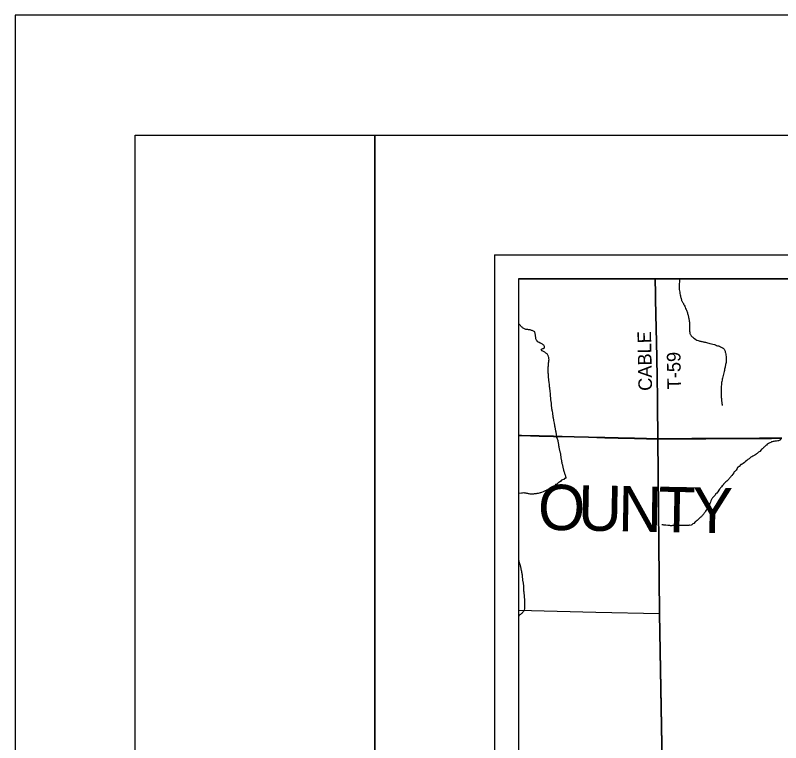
# Model space of a CAD drawing. Extents: x 0 to 34, y 0 to 22.
# Drawn here: x 0 to 3.195, y 18.962 to 22 of the extents above; entities that cross this region are included whole.
import ezdxf

# ---------------------------------------------------------------- set-up
doc = ezdxf.new("R2010")
doc.units = 0
for name, color, linetype in [('GM_X_Corporation', 7, 'Continuous'), ('GM_X_County_Text', 7, 'Continuous'), ('GM_X_Minor_River', 7, 'Continuous'), ('GM_X_Township_Road', 7, 'Continuous'), ('GM_X_Township_Road_Text', 7, 'Continuous'), ('SH_Border', 7, 'Continuous'), ('SH_Cut_Line', 7, 'Continuous'), ('SH_Data', 7, 'Continuous')]:
    doc.layers.add(name, color=color, linetype=linetype)

msp = doc.modelspace()

# ---------------------------------------------------------------- linework, layer by layer
at = {"layer": 'GM_X_Corporation'}
for points in [[(7.8853, 20.9), (2.1, 20.9), (2.1, 20.2456), (2.1124, 20.2453), (2.187, 20.2434), (2.246, 20.2419), (2.2833, 20.2411), (2.333, 20.2398), (2.3921, 20.2383), (2.4604, 20.2364), (2.5164, 20.2351), (2.535, 20.2346), (2.5847, 20.2334), (2.6344, 20.2324), (2.6825, 20.2316), (2.7333, 20.2317), (2.8234, 20.2319), (2.8825, 20.2322), (2.9354, 20.2326), (3.0007, 20.2328), (3.0286, 20.2331), (3.1064, 20.2336), (3.1561, 20.2337), (3.1996, 20.2345)], [(7.8853, 20.9), (2.6713, 20.9), (2.6715, 20.8917), (2.672, 20.8451), (2.6728, 20.814), (2.6742, 20.7519), (2.6766, 20.6339), (2.6773, 20.5717), (2.679, 20.4847), (2.6801, 20.4041), (2.6808, 20.3576), (2.6821, 20.252), (2.6825, 20.2316), (2.7333, 20.2317), (2.8234, 20.2319), (2.8825, 20.2322), (2.9354, 20.2326), (3.0007, 20.2328), (3.0286, 20.2331), (3.1064, 20.2336), (3.1561, 20.2337), (3.1996, 20.2345)], [(3.1996, 20.2345), (3.1561, 20.2337), (3.1064, 20.2336), (3.0286, 20.2331), (3.0007, 20.2328), (2.9354, 20.2326), (2.8825, 20.2322), (2.8234, 20.2319), (2.7333, 20.2317), (2.6825, 20.2316), (2.6344, 20.2324), (2.5847, 20.2334), (2.535, 20.2346), (2.5164, 20.2351), (2.4604, 20.2364), (2.3921, 20.2383), (2.333, 20.2398), (2.2833, 20.2411), (2.246, 20.2419), (2.187, 20.2434), (2.1124, 20.2453), (2.1, 20.2456), (2.1, 14.1)], [(3.1996, 20.2345), (3.1561, 20.2337), (3.1064, 20.2336), (3.0286, 20.2331), (3.0007, 20.2328), (2.9354, 20.2326), (2.8825, 20.2322), (2.8234, 20.2319), (2.7333, 20.2317), (2.6825, 20.2316), (2.6883, 19.5017), (2.7024, 18.7188), (2.7184, 17.7156), (2.7304, 16.9599), (2.7477, 15.8824), (2.7366, 15.2014)]]:
    msp.add_lwpolyline(points, dxfattribs=at)
for points in [[(2.6713, 20.9), (2.1, 20.9), (2.1, 20.2456), (2.1124, 20.2453), (2.187, 20.2434), (2.246, 20.2419), (2.2833, 20.2411), (2.333, 20.2398), (2.3921, 20.2383), (2.4604, 20.2364), (2.5164, 20.2351), (2.535, 20.2346), (2.5847, 20.2334), (2.6344, 20.2324), (2.6825, 20.2316), (2.6821, 20.252), (2.6808, 20.3576), (2.6801, 20.4041), (2.679, 20.4847), (2.6773, 20.5717), (2.6766, 20.6339), (2.6742, 20.7519), (2.6728, 20.814), (2.672, 20.8451), (2.6715, 20.8917)], [(2.1, 20.2456), (2.1, 15.2121), (2.7366, 15.2014), (2.7477, 15.8824), (2.7304, 16.9599), (2.7184, 17.7156), (2.7024, 18.7188), (2.6883, 19.5017), (2.6825, 20.2316), (2.6344, 20.2324), (2.5847, 20.2334), (2.535, 20.2346), (2.5164, 20.2351), (2.4604, 20.2364), (2.3921, 20.2383), (2.333, 20.2398), (2.2833, 20.2411), (2.246, 20.2419), (2.187, 20.2434), (2.1124, 20.2453)]]:
    msp.add_lwpolyline(points, close=True, dxfattribs=at)
at = {"layer": 'GM_X_Minor_River'}
for points in [[(2.7733, 20.9), (2.7733, 20.8993), (2.7729, 20.8944), (2.7726, 20.8898), (2.7723, 20.8852), (2.7716, 20.8803), (2.7712, 20.8757), (2.7709, 20.8715), (2.7709, 20.8677), (2.771, 20.8643), (2.771, 20.8609), (2.7714, 20.8574), (2.7714, 20.8544), (2.7719, 20.8491), (2.7731, 20.8441), (2.7739, 20.8384), (2.7751, 20.8331), (2.7759, 20.8286), (2.7771, 20.8244), (2.7779, 20.821), (2.7787, 20.8179), (2.7794, 20.8153), (2.7802, 20.8134), (2.7806, 20.8111), (2.7814, 20.8092), (2.7822, 20.8069), (2.7834, 20.8047), (2.7845, 20.8024), (2.7861, 20.8001), (2.7872, 20.7982), (2.7884, 20.796), (2.7895, 20.7941), (2.7911, 20.7918), (2.7923, 20.7888), (2.7942, 20.7854), (2.7961, 20.7812), (2.7977, 20.7759), (2.8, 20.7717), (2.8016, 20.7679), (2.8051, 20.7577), (2.8059, 20.7543), (2.8067, 20.7509), (2.8079, 20.7478), (2.8087, 20.7452), (2.8094, 20.7425), (2.8098, 20.7403), (2.8106, 20.7372), (2.8114, 20.7346), (2.8118, 20.7315), (2.8122, 20.7281), (2.813, 20.7247), (2.8131, 20.722), (2.8135, 20.7186), (2.8139, 20.7159), (2.8139, 20.7125), (2.814, 20.7083), (2.8144, 20.7045), (2.8144, 20.7003)], [(2.2041, 20.6091), (2.2071, 20.6099), (2.2086, 20.6137), (2.2086, 20.6168), (2.2074, 20.6191), (2.2055, 20.6217), (2.2032, 20.6243), (2.2005, 20.6266), (2.1978, 20.6281), (2.1951, 20.6296), (2.1932, 20.6307), (2.1906, 20.6314), (2.1871, 20.6341), (2.1841, 20.6356), (2.1814, 20.6367), (2.1775, 20.6412), (2.1752, 20.6431), (2.1733, 20.6491), (2.1725, 20.6529), (2.1721, 20.6564), (2.1717, 20.659), (2.1709, 20.6609), (2.1709, 20.6628), (2.1708, 20.6659), (2.1704, 20.6689), (2.17, 20.6708), (2.1696, 20.6727), (2.1692, 20.6754), (2.168, 20.6776), (2.1661, 20.6791), (2.1634, 20.681), (2.1577, 20.6832), (2.1543, 20.6843), (2.1516, 20.6851), (2.1486, 20.6858), (2.1459, 20.6865), (2.1436, 20.6869), (2.1417, 20.6869), (2.1398, 20.6872), (2.1368, 20.6876), (2.1337, 20.6875), (2.1315, 20.6875), (2.1276, 20.6894), (2.1253, 20.6905), (2.1223, 20.692), (2.12, 20.6935), (2.1173, 20.6954), (2.115, 20.6972), (2.1131, 20.6991), (2.1104, 20.7021), (2.1089, 20.704), (2.1066, 20.7067), (2.1046, 20.7085), (2.1031, 20.7104), (2.1004, 20.7131), (2.1, 20.7135)], [(2.8144, 20.7003), (2.8141, 20.6969), (2.8141, 20.6939), (2.8141, 20.6905), (2.8142, 20.687), (2.8142, 20.6836), (2.8142, 20.6802), (2.815, 20.6771), (2.8154, 20.6741), (2.8162, 20.6711), (2.817, 20.6688), (2.8182, 20.6665), (2.8197, 20.6639), (2.8213, 20.662), (2.8224, 20.6601), (2.8247, 20.6578), (2.8274, 20.6552), (2.8309, 20.6526), (2.8355, 20.6496), (2.8401, 20.6466), (2.845, 20.6436), (2.85, 20.6417), (2.8538, 20.6403), (2.8572, 20.6392), (2.8618, 20.6384), (2.8645, 20.6381), (2.8671, 20.6374), (2.8706, 20.6366), (2.874, 20.6363), (2.8774, 20.6352), (2.8808, 20.6345), (2.8847, 20.6334), (2.8991, 20.6293), (2.9064, 20.6275), (2.9121, 20.626), (2.9178, 20.6246), (2.9228, 20.6231), (2.9274, 20.6216), (2.9316, 20.6201), (2.9357, 20.619), (2.9396, 20.6176), (2.943, 20.6161), (2.9464, 20.6146), (2.9495, 20.6131), (2.9514, 20.612), (2.9537, 20.6105), (2.9556, 20.609), (2.9583, 20.6056), (2.9598, 20.6033), (2.961, 20.6003), (2.9626, 20.5973), (2.9634, 20.5938), (2.9645, 20.5897), (2.9654, 20.5851), (2.9662, 20.5805), (2.967, 20.5752), (2.9674, 20.571), (2.9678, 20.5669), (2.9675, 20.5631), (2.9675, 20.5589), (2.9672, 20.5543), (2.9668, 20.5501), (2.9661, 20.5459), (2.965, 20.5417), (2.9643, 20.5379), (2.9632, 20.5349), (2.9629, 20.5303), (2.9618, 20.5257), (2.9607, 20.5215), (2.9596, 20.5169), (2.9585, 20.512), (2.9574, 20.5066), (2.9559, 20.5017), (2.9548, 20.496), (2.9534, 20.4902), (2.9519, 20.4849), (2.9508, 20.4807), (2.9501, 20.4765), (2.949, 20.4708), (2.9483, 20.4666), (2.948, 20.462), (2.9462, 20.4456), (2.9463, 20.4399), (2.9463, 20.4338), (2.9464, 20.4293), (2.9464, 20.4239), (2.9465, 20.4186), (2.9466, 20.4125), (2.947, 20.408), (2.947, 20.4034), (2.9474, 20.3992), (2.9479, 20.3954), (2.9479, 20.3916), (2.9483, 20.3882), (2.9487, 20.3852), (2.9491, 20.3821), (2.9495, 20.3802), (2.9496, 20.3779), (2.9503, 20.3757), (2.9507, 20.3734), (2.9511, 20.3715)], [(2.26, 20.2397), (2.2603, 20.2345), (2.2602, 20.2429), (2.2594, 20.2478), (2.259, 20.2497), (2.2578, 20.2592), (2.2566, 20.2638), (2.2558, 20.266), (2.2554, 20.2691), (2.255, 20.2717), (2.2542, 20.2744), (2.2538, 20.2771), (2.253, 20.2805), (2.2526, 20.2839), (2.2518, 20.2892), (2.251, 20.2926), (2.2502, 20.2964), (2.2482, 20.3074), (2.2474, 20.3116), (2.2466, 20.3147), (2.2461, 20.3181), (2.2457, 20.3219), (2.2449, 20.3268), (2.2441, 20.3337), (2.2433, 20.3394), (2.2425, 20.3447), (2.2413, 20.3492), (2.2405, 20.3527), (2.2401, 20.3565), (2.2393, 20.3602), (2.2389, 20.3633), (2.2388, 20.3667), (2.2384, 20.3701), (2.238, 20.3743), (2.2376, 20.3796), (2.2367, 20.3876), (2.2359, 20.3945), (2.2355, 20.399), (2.235, 20.4032), (2.2346, 20.4066), (2.2342, 20.4093), (2.2338, 20.4127), (2.2338, 20.4169), (2.2333, 20.4222), (2.2329, 20.4272), (2.2325, 20.431), (2.2321, 20.4351), (2.2317, 20.4374), (2.2316, 20.4401), (2.2312, 20.4435), (2.2304, 20.4477), (2.23, 20.4515), (2.2296, 20.4553), (2.2291, 20.4598), (2.2283, 20.4644), (2.2279, 20.4686), (2.2275, 20.4724), (2.2271, 20.4758), (2.2267, 20.4811), (2.2262, 20.4849), (2.2262, 20.4891), (2.2258, 20.4929), (2.2254, 20.4967), (2.2249, 20.5009), (2.2245, 20.5051), (2.224, 20.5138), (2.2247, 20.5203), (2.2247, 20.5245), (2.2243, 20.5268), (2.2242, 20.5317), (2.225, 20.5367), (2.2249, 20.5401), (2.2253, 20.5428), (2.2256, 20.5454), (2.226, 20.5481), (2.226, 20.55), (2.2263, 20.5519), (2.227, 20.5595), (2.2277, 20.5618), (2.2273, 20.5671), (2.2269, 20.569), (2.2269, 20.5713), (2.2261, 20.574), (2.2245, 20.5793), (2.2234, 20.5812), (2.2218, 20.5834), (2.2195, 20.5857), (2.2172, 20.5876), (2.2149, 20.5887), (2.2115, 20.5917), (2.2096, 20.5936), (2.2073, 20.5951), (2.2054, 20.5962), (2.2023, 20.5973), (2.1996, 20.5984), (2.1973, 20.5992), (2.195, 20.6018), (2.1973, 20.6056), (2.1995, 20.6068), (2.2022, 20.608), (2.2041, 20.6091)], [(2.9511, 20.3715), (2.9515, 20.3703)], [(2.2604, 20.2397), (2.2604, 20.2373), (2.2619, 20.2312), (2.2631, 20.2282), (2.2642, 20.224), (2.2649, 20.2206), (2.2657, 20.2168), (2.2661, 20.213), (2.2668, 20.2099), (2.2672, 20.2077), (2.2676, 20.2035), (2.2683, 20.1989), (2.2687, 20.1955), (2.2695, 20.1924), (2.2702, 20.1905), (2.2706, 20.1883), (2.2714, 20.1852), (2.2721, 20.1822), (2.2729, 20.1795), (2.2733, 20.1769), (2.274, 20.1746), (2.2744, 20.1723), (2.2752, 20.17), (2.2755, 20.1677), (2.2755, 20.1654), (2.2763, 20.162), (2.2767, 20.1586), (2.277, 20.1555), (2.2774, 20.1525), (2.2789, 20.1453), (2.2793, 20.1422), (2.2801, 20.1396), (2.2804, 20.1365), (2.2812, 20.1327), (2.2819, 20.1282), (2.2827, 20.1255), (2.2835, 20.1232), (2.2838, 20.1209), (2.2842, 20.1183), (2.285, 20.116), (2.2854, 20.1133), (2.2857, 20.111), (2.2865, 20.1088), (2.2869, 20.1061), (2.2876, 20.1027), (2.2884, 20.1004), (2.2899, 20.0958), (2.291, 20.092), (2.2922, 20.089), (2.2929, 20.0871), (2.2941, 20.084), (2.2948, 20.0799), (2.296, 20.0772), (2.2963, 20.0753), (2.2971, 20.0734), (2.2975, 20.07), (2.2975, 20.0673), (2.2956, 20.0658), (2.2921, 20.065), (2.2895, 20.062), (2.2834, 20.0593), (2.28, 20.0586), (2.2769, 20.0548), (2.2716, 20.0498), (2.2674, 20.0494), (2.2632, 20.0445), (2.2583, 20.0411), (2.2549, 20.0399), (2.2541, 20.0369), (2.248, 20.0331), (2.2419, 20.0301), (2.2385, 20.0282), (2.2351, 20.0255), (2.2305, 20.0229), (2.2264, 20.0206), (2.2233, 20.0191), (2.2207, 20.0175), (2.2176, 20.0164), (2.2153, 20.0153), (2.2119, 20.0137), (2.2092, 20.0126), (2.2066, 20.0111), (2.2028, 20.0099), (2.1963, 20.0069), (2.1925, 20.0054), (2.1902, 20.005), (2.1864, 20.0039), (2.1826, 20.0031), (2.1796, 20.0027), (2.1766, 20.0027), (2.1743, 20.002), (2.1724, 20.0016), (2.1701, 20.0016), (2.1674, 20.0012), (2.1652, 20.0009), (2.1625, 20.0005), (2.1598, 20.0005), (2.1568, 20.0005), (2.1541, 20.0005), (2.1515, 20.0005), (2.1496, 20.0005)], [(3.194, 20.2329), (3.194, 20.2274), (3.1917, 20.2259), (3.1883, 20.2236), (3.1857, 20.2229), (3.183, 20.2225), (3.1777, 20.2221), (3.1754, 20.2217), (3.1727, 20.2217), (3.1697, 20.2214), (3.1659, 20.2206), (3.164, 20.2206), (3.1598, 20.2187), (3.1571, 20.218), (3.1541, 20.2164), (3.1492, 20.2149), (3.1438, 20.2115), (3.14, 20.2092), (3.1378, 20.2088), (3.1355, 20.2054), (3.1321, 20.2031), (3.129, 20.1993), (3.1252, 20.1959), (3.1225, 20.1952), (3.1218, 20.1929), (3.1184, 20.1898), (3.1149, 20.1872), (3.1127, 20.1853), (3.1081, 20.1784), (3.1024, 20.175), (3.099, 20.1727), (3.0963, 20.1705), (3.094, 20.1686), (3.091, 20.1659), (3.0872, 20.1632), (3.0838, 20.1613), (3.0807, 20.1598), (3.0784, 20.1587), (3.0742, 20.156), (3.0708, 20.1541), (3.0689, 20.1526), (3.0663, 20.1503), (3.0632, 20.1481), (3.0602, 20.1458), (3.0575, 20.1446), (3.0537, 20.1405), (3.048, 20.1363), (3.0431, 20.1317), (3.0377, 20.1287), (3.0339, 20.126), (3.0309, 20.1245), (3.029, 20.1234), (3.0218, 20.1161), (3.0172, 20.1127), (3.0145, 20.1108), (3.0138, 20.1078), (3.0084, 20.1002), (3.0035, 20.0949), (3.0012, 20.0937), (2.9997, 20.0895), (2.9955, 20.0838), (2.9913, 20.0778), (2.9871, 20.0743), (2.9849, 20.0709), (2.9822, 20.0683), (2.9803, 20.0652), (2.978, 20.0626), (2.9761, 20.0599), (2.9738, 20.0584), (2.97, 20.0542), (2.9658, 20.0515), (2.9628, 20.0493), (2.9613, 20.047), (2.959, 20.0443), (2.9563, 20.0417), (2.954, 20.0382), (2.951, 20.0344), (2.9476, 20.0314), (2.9457, 20.0291), (2.9438, 20.0268), (2.9419, 20.0234), (2.9392, 20.0207), (2.9365, 20.0162), (2.9324, 20.0093), (2.9278, 20.0036), (2.9247, 20.0014), (2.9232, 19.9995), (2.9209, 19.9957), (2.9107, 19.9846), (2.9091, 19.9827), (2.9076, 19.9805), (2.9061, 19.9778), (2.905, 19.9751), (2.9038, 19.9721), (2.9023, 19.9668), (2.8996, 19.9611), (2.8977, 19.9573), (2.897, 19.955), (2.8958, 19.9523), (2.8947, 19.9497), (2.8928, 19.9462)], [(2.1496, 20.0005), (2.145, 20.0016), (2.142, 20.002), (2.1389, 20.0028), (2.137, 20.0032), (2.1351, 20.0035), (2.1329, 20.0039), (2.1298, 20.0043), (2.1272, 20.0047), (2.1245, 20.0051), (2.1226, 20.0054), (2.1165, 20.0047), (2.1135, 20.0043), (2.1028, 20.0032), (2.1009, 20.0032), (2.1, 20.003)], [(2.8928, 19.9462), (2.8901, 19.9421), (2.8874, 19.9379), (2.8844, 19.9337), (2.8813, 19.9291), (2.8783, 19.9242), (2.8756, 19.9208), (2.8734, 19.9177), (2.8718, 19.9155), (2.8703, 19.9136), (2.868, 19.9113), (2.865, 19.9079), (2.8631, 19.9063), (2.8612, 19.9044), (2.8585, 19.9025), (2.8559, 19.8999), (2.8532, 19.8976), (2.8513, 19.8961), (2.8486, 19.893), (2.8456, 19.89), (2.8425, 19.8873), (2.8403, 19.8854), (2.8384, 19.8843), (2.8327, 19.8778), (2.8285, 19.8759), (2.8262, 19.8748), (2.8239, 19.8725), (2.8209, 19.8706), (2.8163, 19.8699), (2.8144, 19.8702), (2.8125, 19.8702), (2.8095, 19.8699), (2.8072, 19.8699), (2.8045, 19.8699), (2.8015, 19.8699), (2.7988, 19.8699), (2.7962, 19.8695), (2.7931, 19.8695), (2.7901, 19.8691), (2.7867, 19.8691), (2.784, 19.8691), (2.7806, 19.8691), (2.7775, 19.8691), (2.7749, 19.8695), (2.7726, 19.8695), (2.7699, 19.8695), (2.7669, 19.8699), (2.7639, 19.8699), (2.7604, 19.8699), (2.7574, 19.8699), (2.7528, 19.8695), (2.7498, 19.8692), (2.7464, 19.8692), (2.7433, 19.8688), (2.7403, 19.8684), (2.7373, 19.8684), (2.7346, 19.8684), (2.7316, 19.8688), (2.7289, 19.8692), (2.7259, 19.8692), (2.7232, 19.8696), (2.7152, 19.8703), (2.713, 19.8703), (2.7111, 19.8707), (2.7088, 19.8711), (2.7065, 19.8711), (2.7042, 19.8715), (2.7012, 19.8719), (2.6993, 19.8715), (2.6989, 19.8715)], [(2.1, 19.7271), (2.1003, 19.7263), (2.1014, 19.7221), (2.1022, 19.7191), (2.1029, 19.7168), (2.1037, 19.7145), (2.1044, 19.7122), (2.1052, 19.7096), (2.1059, 19.7069), (2.1067, 19.7046), (2.1071, 19.7023), (2.1078, 19.7001), (2.1082, 19.6982), (2.109, 19.6951), (2.1097, 19.6928), (2.1101, 19.6902), (2.1105, 19.6875), (2.1109, 19.6848), (2.1116, 19.6829), (2.1124, 19.6788), (2.1131, 19.6765), (2.1135, 19.6738), (2.1139, 19.6708), (2.1143, 19.6674), (2.115, 19.6632), (2.1154, 19.6594), (2.1158, 19.6556), (2.1161, 19.6521), (2.1165, 19.6491), (2.1169, 19.6457), (2.1173, 19.6426), (2.1177, 19.64), (2.1184, 19.6373), (2.1188, 19.6346), (2.1192, 19.6316), (2.1195, 19.6274), (2.1203, 19.6247), (2.1207, 19.6221), (2.1211, 19.6198), (2.121, 19.6175), (2.121, 19.6145), (2.1214, 19.6111)], [(2.1214, 19.6111), (2.1214, 19.6073), (2.1214, 19.6038), (2.1218, 19.6), (2.1218, 19.5962), (2.1225, 19.5928), (2.1233, 19.589), (2.1233, 19.586), (2.1237, 19.5768), (2.124, 19.5742), (2.124, 19.5707), (2.1244, 19.5677), (2.1248, 19.5643), (2.1248, 19.5616), (2.1252, 19.5586), (2.1255, 19.5548), (2.1259, 19.5525), (2.1259, 19.5506), (2.1259, 19.5475), (2.1259, 19.5449), (2.1259, 19.5422), (2.1259, 19.5399), (2.1259, 19.538), (2.1259, 19.5357), (2.1259, 19.5331), (2.1255, 19.5304), (2.1255, 19.5281), (2.1255, 19.5262), (2.1255, 19.524), (2.1255, 19.5209), (2.124, 19.516), (2.1225, 19.5141), (2.1209, 19.5107), (2.119, 19.5072), (2.1171, 19.5057), (2.1156, 19.5038), (2.1133, 19.5023), (2.1107, 19.4996), (2.1084, 19.4981), (2.1053, 19.4955), (2.1031, 19.4932), (2.1012, 19.4909), (2.1, 19.4899)]]:
    msp.add_lwpolyline(points, dxfattribs=at)
at = {"layer": 'GM_X_Township_Road'}
for points in [[(2.6827, 20.2311), (2.6824, 20.2514), (2.681, 20.357), (2.6803, 20.4036), (2.6792, 20.4842), (2.6775, 20.5712), (2.6768, 20.6333), (2.6745, 20.7513), (2.673, 20.8135), (2.6722, 20.8445), (2.6717, 20.8911), (2.6715, 20.9)], [(2.1, 20.2451), (2.1126, 20.2447), (2.1872, 20.2428), (2.2463, 20.2413), (2.2836, 20.2405), (2.3333, 20.2392), (2.3923, 20.2377), (2.4606, 20.2359), (2.5166, 20.2345), (2.5352, 20.2341), (2.5849, 20.2329), (2.6347, 20.2318), (2.6827, 20.2311)], [(2.6827, 20.2311), (2.7335, 20.2311), (2.8237, 20.2314), (2.8827, 20.2316), (2.9356, 20.232), (3.0009, 20.2322), (3.0289, 20.2326), (3.1066, 20.233), (3.1563, 20.2331), (3.1998, 20.2339)], [(2.697, 19.0294), (2.6885, 19.5012), (2.6827, 20.2311)], [(2.1, 19.5153), (2.4226, 19.5071), (2.6885, 19.5012)], [(2.7186, 17.715), (2.7026, 18.7182), (2.697, 19.0294)]]:
    msp.add_lwpolyline(points, dxfattribs=at)
at = {"layer": 'SH_Border'}
for points in [[(0.5, 21.5), (1.5, 21.5), (1.5, 0.5), (0.5, 0.5)], [(1.5, 21.5), (33.5, 21.5), (33.5, 0.5), (1.5, 0.5)]]:
    msp.add_lwpolyline(points, close=True, dxfattribs=at)
at = {"layer": 'SH_Cut_Line'}
msp.add_lwpolyline([(0, 0), (34, 0), (34, 22), (0, 22)], close=True, dxfattribs=at)
at = {"layer": 'SH_Data'}
for p, q in [((2, 21), (9, 21)), ((2, 21), (2, 14)), ((2.1, 20.9), (2.1, 14.1)), ((2.1, 20.9), (8.9, 20.9))]:
    msp.add_line(p, q, dxfattribs=at)

# ---------------------------------------------------------------- texts
at = {"layer": 'GM_X_County_Text'}
for s, rotation, p in [('O', 358.9038, (2.1801, 19.8518)), ('U', 358.9017, (2.3475, 19.8486)), ('N', 358.9042, (2.515, 19.8454)), ('T', 358.902, (2.6825, 19.8422)), ('Y', 358.9042, (2.8241, 19.8395))]:
    msp.add_text(s, height=0.1894, rotation=rotation, dxfattribs=at).set_placement(p)
at = {"layer": 'GM_X_Township_Road_Text'}
for s, rotation, p in [('CABLE', 91.0457, (2.658, 20.4322)), ('T-59', 91.0669, (2.779, 20.4386))]:
    msp.add_text(s, height=0.05682, rotation=rotation, dxfattribs=at).set_placement(p)

doc.saveas('drawing.dxf')
